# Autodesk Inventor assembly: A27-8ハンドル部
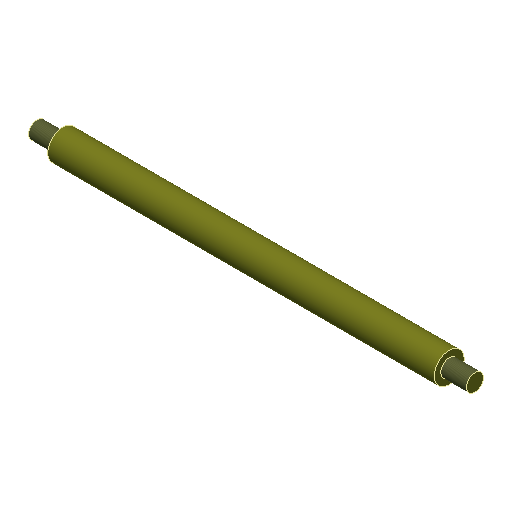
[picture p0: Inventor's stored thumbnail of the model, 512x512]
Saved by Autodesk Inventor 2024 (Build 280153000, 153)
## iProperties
Created: 2008-07
Part Number: A27-8ハンドル部
Document SubType Name: Assembly
Designer: y-shimohigashi
Stock Number: A24-8ハンドル部
Author: y-shimohigashi
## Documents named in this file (2)
- C:\Users\m-fujimoto\Desktop\Inventor2024基礎コース\練習問題\練習問題-27\A27-8ハンドル部.iam
- C:\Users\m-fujimoto\Desktop\Inventor2024基礎コース\練習問題\練習問題-27\P27-9ハンドル.ipt
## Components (1 placed, 1 different names)
1. P27-9ハンドル:1
